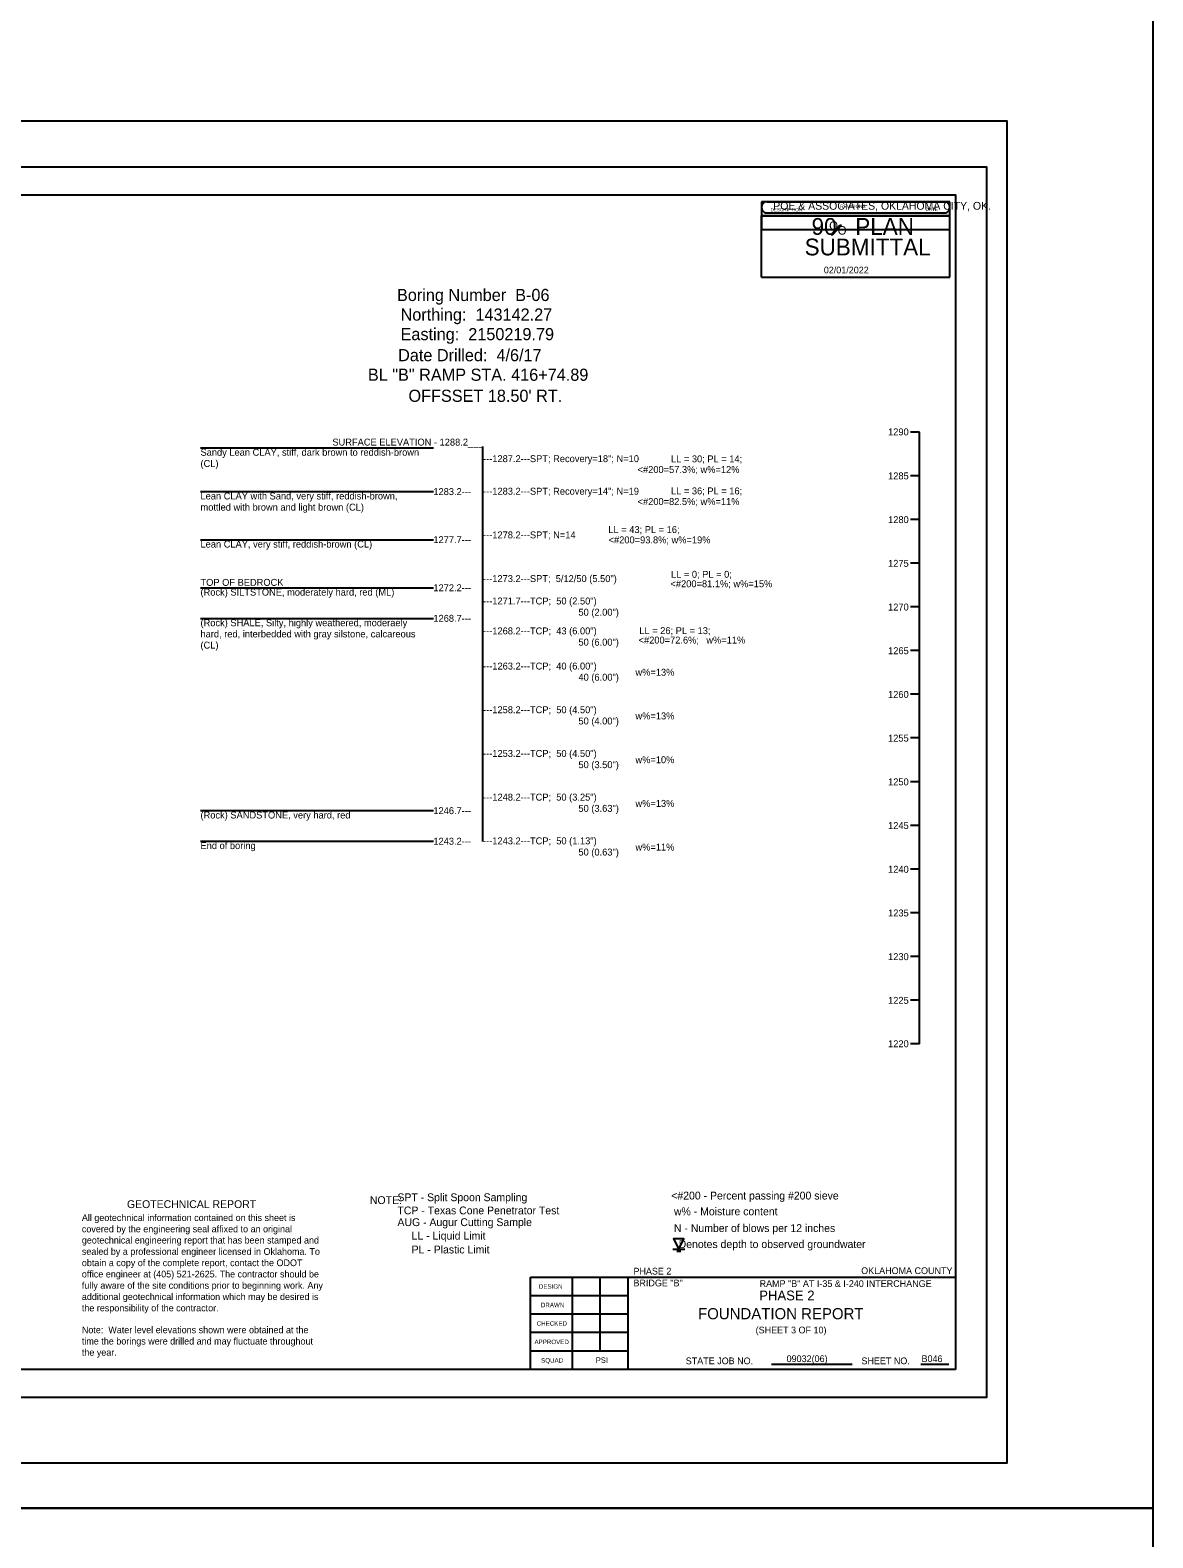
# Model space of a CAD drawing. Extents: x 2150162 to 2150245, y 143729 to 143865.
# Drawn here: x 2150183.34 to 2150203.4, y 143783.81 to 143810.76 of the extents above; entities that cross this region are included whole.
import ezdxf

# ---------------------------------------------------------------- set-up
doc = ezdxf.new("R2010")
doc.units = 0
for name, color, linetype in [('Default', 7, 'Continuous'), ('S', 7, 'Continuous'), ('SHT_Plot_Shape_Full', 7, 'Continuous'), ('SHT_Plot_Shape_Half', 7, 'Continuous'), ('SHT_Sheet_Border', 7, 'Continuous'), ('SHT_Stamp_90_Submit', 7, 'Continuous'), ('SHT_Stamp_Rev_Block', 7, 'Continuous'), ('SHT_Standard_Sheet_Lines', 7, 'Continuous'), ('SHT_Standard_Sheet_Txt', 7, 'Continuous'), ('T', 7, 'Continuous'), ('T-Title', 7, 'Continuous'), ('Text', 7, 'Continuous')]:
    doc.layers.add(name, color=color, linetype=linetype)

# ---------------------------------------------------------------- blocks, each defined once
blk = doc.blocks.new('DGRFC_WTLEV1')
at = {"layer": 'Default'}
for points in [[(-0.0127, 0), (0.0127, 0)], [(0, 0), (0.0106, 0.0212), (-0.0106, 0.0212), (0, 0)], [(-0.0042, -0.0042), (0.0042, -0.0042)]]:
    blk.add_lwpolyline(points, dxfattribs=at)

msp = doc.modelspace()

# ---------------------------------------------------------------- linework, layer by layer
at = {"layer": 'Default'}
msp.add_line((2150199.236, 143792.641), (2150199.236, 143803.578), dxfattribs=at)
for points in [[(2150199.236, 143803.578), (2150199.07, 143803.578)], [(2150186.383, 143803.295), (2150190.55, 143803.295)], [(2150191.421, 143803.322), (2150191.421, 143796.259)], [(2150199.236, 143802.797), (2150199.07, 143802.797)], [(2150186.383, 143802.513), (2150190.55, 143802.513)], [(2150199.236, 143802.015), (2150199.07, 143802.015)], [(2150186.383, 143801.654), (2150190.55, 143801.654)], [(2150199.236, 143801.234), (2150199.07, 143801.234)], [(2150186.383, 143800.795), (2150190.55, 143800.795)], [(2150199.236, 143800.453), (2150199.07, 143800.453)], [(2150186.383, 143800.248), (2150190.55, 143800.248)], [(2150199.236, 143799.672), (2150199.07, 143799.672)], [(2150199.236, 143798.891), (2150199.07, 143798.891)], [(2150199.236, 143798.109), (2150199.07, 143798.109)], [(2150199.236, 143797.328), (2150199.07, 143797.328)], [(2150186.383, 143796.81), (2150190.55, 143796.81)], [(2150199.236, 143796.547), (2150199.07, 143796.547)], [(2150186.383, 143796.263), (2150190.55, 143796.263)], [(2150199.236, 143795.766), (2150199.07, 143795.766)], [(2150199.236, 143794.984), (2150199.07, 143794.984)], [(2150199.236, 143794.203), (2150199.07, 143794.203)], [(2150199.236, 143793.422), (2150199.07, 143793.422)], [(2150199.236, 143792.641), (2150199.07, 143792.641)]]:
    msp.add_lwpolyline(points, dxfattribs=at)
at = {"layer": 'S'}
for points in [[(2150203.404, 143784.341), (2150161.568, 143784.341), (2150161.568, 143865.061), (2150203.404, 143865.061)], [(2150161.568, 143784.341), (2150203.404, 143784.341), (2150203.404, 143729.315), (2150161.568, 143729.315)]]:
    msp.add_lwpolyline(points, close=True, dxfattribs=at)
at = {"layer": 'SHT_Plot_Shape_Full'}
msp.add_lwpolyline([(2150164.792, 143809.144), (2150200.792, 143809.144), (2150200.792, 143785.144), (2150164.792, 143785.144)], close=True, dxfattribs=at)
at = {"layer": 'SHT_Plot_Shape_Half'}
msp.add_lwpolyline([(2150166.429, 143808.319), (2150200.429, 143808.319), (2150200.429, 143786.319), (2150166.429, 143786.319)], close=True, dxfattribs=at)
at = {"layer": 'SHT_Sheet_Border'}
for p, q in [((2150192.279, 143786.819), (2150192.279, 143788.469)), ((2150192.279, 143788.469), (2150199.879, 143788.469)), ((2150194.029, 143786.819), (2150194.029, 143788.47))]:
    msp.add_line(p, q, dxfattribs=at)
msp.add_lwpolyline([(2150199.879, 143786.819), (2150168.379, 143786.819), (2150168.379, 143807.819), (2150199.879, 143807.819)], close=True, dxfattribs=at)
at = {"layer": 'SHT_Stamp_90_Submit'}
for p, q in [((2150196.51, 143807.695), (2150199.676, 143807.695)), ((2150196.41, 143807.445), (2150199.776, 143807.445)), ((2150196.41, 143806.346), (2150196.41, 143807.445)), ((2150196.51, 143807.495), (2150199.676, 143807.495)), ((2150199.776, 143806.346), (2150199.776, 143807.445)), ((2150197.653, 143807.107), (2150197.809, 143807.279)), ((2150197.653, 143807.107), (2150197.684, 143807.107)), ((2150197.671, 143807.107), (2150197.827, 143807.279)), ((2150197.676, 143807.107), (2150197.832, 143807.279)), ((2150197.684, 143807.107), (2150197.839, 143807.279)), ((2150197.809, 143807.279), (2150197.839, 143807.279)), ((2150196.41, 143806.346), (2150199.776, 143806.346))]:
    msp.add_line(p, q, dxfattribs=at)
for centre, start, end in [((2150196.51, 143807.595), 89.9952, 270), ((2150199.676, 143807.595), 270, 90.0048)]:
    msp.add_arc(centre, 0.1, start, end, dxfattribs=at)
at = {"layer": 'SHT_Stamp_Rev_Block'}
for p, q in [((2150196.41, 143807.695), (2150196.41, 143807.195)), ((2150199.776, 143807.695), (2150196.41, 143807.695)), ((2150199.776, 143807.195), (2150199.776, 143807.695)), ((2150199.776, 143807.445), (2150196.41, 143807.445)), ((2150199.776, 143807.195), (2150196.41, 143807.195))]:
    msp.add_line(p, q, dxfattribs=at)
at = {"layer": 'SHT_Standard_Sheet_Lines'}
for p, q in [((2150193.029, 143786.819), (2150193.029, 143788.47)), ((2150193.529, 143787.149), (2150193.529, 143788.47)), ((2150196.59, 143786.915), (2150198.03, 143786.915)), ((2150199.255, 143786.915), (2150199.757, 143786.915))]:
    msp.add_line(p, q, dxfattribs=at)
for points in [[(2150194.029, 143788.139), (2150192.279, 143788.139)], [(2150194.029, 143787.809), (2150192.279, 143787.809)], [(2150194.029, 143787.479), (2150192.279, 143787.479)], [(2150194.029, 143787.149), (2150192.279, 143787.149)]]:
    msp.add_lwpolyline(points, dxfattribs=at)

# ---------------------------------------------------------------- block references
at = {"layer": 'Default', "xscale": 8.503919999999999, "yscale": 8.503919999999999}
msp.add_blockref('DGRFC_WTLEV1', (2150194.93, 143788.973), dxfattribs=at)

# ---------------------------------------------------------------- texts
at = {"layer": 'Default'}
for s, height, p in [('Boring Number  B-06', 0.217, (2150189.895, 143805.92)), ('Northing:  143142.27', 0.217, (2150189.959, 143805.57)), ('Easting:  2150219.79', 0.217, (2150189.959, 143805.22)), ('Date Drilled:  4/6/17', 0.217, (2150189.915, 143804.844)), ('BL "B" RAMP STA. 416+74.89', 0.217, (2150189.375, 143804.494)), ("OFFSSET 18.50' RT.", 0.217, (2150190.1, 143804.118)), ('1290', 0.124, (2150198.672, 143803.519)), ('Sandy Lean CLAY, stiff, dark brown to reddish-brown', 0.124, (2150186.383, 143803.154)), ('SURFACE ELEVATION - 1288.2___', 0.124, (2150188.74, 143803.336)), ('(CL)', 0.124, (2150186.383, 143802.954)), ('---1287.2---SPT; Recovery=18"; N=10', 0.124, (2150191.433, 143803.04)), ('LL = 30; PL = 14;', 0.124, (2150194.792, 143803.036)), ('<#200=57.3%; w%=12%', 0.124, (2150194.195, 143802.846)), ('1285', 0.124, (2150198.672, 143802.732)), ('Lean CLAY with Sand, very stiff, reddish-brown,', 0.124, (2150186.383, 143802.373)), ('1283.2---', 0.124, (2150190.545, 143802.451)), ('---1283.2---SPT; Recovery=14"; N=19', 0.124, (2150191.433, 143802.458)), ('LL = 36; PL = 16;', 0.124, (2150194.792, 143802.463)), ('mottled with brown and light brown (CL)', 0.124, (2150186.383, 143802.173)), ('<#200=82.5%; w%=11%', 0.124, (2150194.195, 143802.273)), ('1280', 0.124, (2150198.672, 143801.95)), ('Lean CLAY, very stiff, reddish-brown (CL)', 0.124, (2150186.383, 143801.513)), ('1277.7---', 0.124, (2150190.545, 143801.592)), ('---1278.2---SPT; N=14', 0.124, (2150191.433, 143801.677)), ('<#200=93.8%; w%=19%', 0.124, (2150193.677, 143801.588)), ('LL = 43; PL = 16;', 0.124, (2150193.673, 143801.773)), ('LL = 0; PL = 0;', 0.124, (2150194.792, 143800.973)), ('1275', 0.124, (2150198.672, 143801.169)), ('TOP OF BEDROCK', 0.124, (2150186.383, 143800.829)), ('1272.2---', 0.124, (2150190.545, 143800.733)), ('---1273.2---SPT;  5/12/50 (5.50")', 0.124, (2150191.433, 143800.896)), ('<#200=81.1%%%; w%%%=15%%%', 0.124, (2150194.783, 143800.804)), ('(Rock) SILTSTONE, moderately hard, red (ML)', 0.124, (2150186.383, 143800.654)), ('---1271.7---TCP;  50 (2.50")', 0.124, (2150191.433, 143800.496)), ('1268.7---', 0.124, (2150190.545, 143800.186)), ('50 (2.00")', 0.124, (2150193.138, 143800.295)), ('1270', 0.124, (2150198.672, 143800.388)), ('(Rock) SHALE, Silty, highly weathered, moderaely', 0.124, (2150186.383, 143800.107)), ('hard, red, interbedded with gray silstone, calcareous', 0.124, (2150186.383, 143799.907)), ('---1268.2---TCP;  43 (6.00")', 0.124, (2150191.433, 143799.961)), ('LL = 26; PL = 13;', 0.124, (2150194.226, 143799.966)), ('(CL)', 0.124, (2150186.383, 143799.707)), ('50 (6.00")', 0.124, (2150193.138, 143799.76)), ('<#200=72.6%;', 0.124, (2150194.213, 143799.797)), ('w%=11%', 0.124, (2150195.424, 143799.798)), ('1265', 0.124, (2150198.672, 143799.607)), ('---1263.2---TCP;  40 (6.00")', 0.124, (2150191.433, 143799.333)), ('40 (6.00")', 0.124, (2150193.138, 143799.133)), ('w%=13%', 0.124, (2150194.157, 143799.222)), ('1260', 0.124, (2150198.672, 143798.825)), ('---1258.2---TCP;  50 (4.50")', 0.124, (2150191.433, 143798.552)), ('50 (4.00")', 0.124, (2150193.138, 143798.351)), ('w%=13%', 0.124, (2150194.157, 143798.441)), ('1255', 0.124, (2150198.672, 143798.044)), ('---1253.2---TCP;  50 (4.50")', 0.124, (2150191.433, 143797.771)), ('50 (3.50")', 0.124, (2150193.138, 143797.57)), ('w%=10%', 0.124, (2150194.157, 143797.659)), ('1250', 0.124, (2150198.672, 143797.263)), ('---1248.2---TCP;  50 (3.25")', 0.124, (2150191.433, 143796.99)), ('(Rock) SANDSTONE, very hard, red', 0.124, (2150186.383, 143796.67)), ('1246.7---', 0.124, (2150190.545, 143796.748)), ('50 (3.63")', 0.124, (2150193.138, 143796.789)), ('w%=13%', 0.124, (2150194.157, 143796.878)), ('1245', 0.124, (2150198.672, 143796.482)), ('End of boring', 0.124, (2150186.383, 143796.123)), ('1243.2---', 0.124, (2150190.545, 143796.201)), ('---1243.2---TCP;  50 (1.13")', 0.124, (2150191.433, 143796.208)), ('50 (0.63")', 0.124, (2150193.138, 143796.008)), ('w%=11%', 0.124, (2150194.157, 143796.097)), ('1240', 0.124, (2150198.672, 143795.7)), ('1235', 0.124, (2150198.672, 143794.919)), ('1230', 0.124, (2150198.672, 143794.138)), ('1225', 0.124, (2150198.672, 143793.357)), ('1220', 0.124, (2150198.672, 143792.581))]:
    msp.add_text(s, height=height, dxfattribs=at).set_placement(p)
at = {"layer": 'Defpoints'}
msp.add_text('PHASE 2', height=0.175, dxfattribs=at).set_placement((2150196.369, 143788.056))
at = {"layer": 'SHT_Stamp_90_Submit'}
for s, height, p in [('POE & ASSOCIATES, OKLAHOMA CITY, OK.', 0.14, (2150196.62, 143807.552)), ('90   PLAN', 0.3, (2150197.305, 143807.103)), ('O', 0.153, (2150197.619, 143807.192)), ('SUBMITTAL', 0.3, (2150197.181, 143806.736)), ('O', 0.153, (2150197.771, 143807.107)), ('02/01/2022', 0.12, (2150197.523, 143806.414))]:
    msp.add_text(s, height=height, dxfattribs=at).set_placement(p)
at = {"layer": 'SHT_Stamp_Rev_Block'}
for s, height, p in [('DESCRIPTION', 0.05999, (2150196.57, 143807.523)), ('REVISIONS', 0.06, (2150197.818, 143807.582)), ('DATE', 0.06, (2150199.34, 143807.527))]:
    msp.add_text(s, height=height, dxfattribs=at).set_placement(p)
at = {"layer": 'SHT_Standard_Sheet_Txt'}
for s, height, p in [('DESIGN', 0.08, (2150192.431, 143788.264)), ('DRAWN', 0.08, (2150192.467, 143787.934)), ('CHECKED', 0.08, (2150192.392, 143787.604)), ('APPROVED', 0.08, (2150192.353, 143787.274)), ('SQUAD', 0.08, (2150192.471, 143786.943)), ('STATE JOB NO.', 0.12, (2150195.056, 143786.915)), ('SHEET NO. ', 0.12, (2150198.196, 143786.915))]:
    msp.add_text(s, height=height, dxfattribs=at).set_placement(p)
at = {"layer": 'T'}
for s, height, p in [('PHASE 2', 0.12, (2150194.121, 143788.518)), ('BRIDGE "B"', 0.12, (2150194.121, 143788.307)), ('OKLAHOMA COUNTY', 0.12, (2150198.191, 143788.526)), ('RAMP "B" AT I-35 & I-240 INTERCHANGE', 0.12, (2150196.376, 143788.296)), ('(SHEET 3 OF 10)', 0.12, (2150196.305, 143787.466)), ('PSI', 0.1, (2150193.449, 143786.937)), ('09032(06)', 0.12, (2150196.859, 143786.953)), ('B046', 0.12, (2150199.27, 143786.953))]:
    msp.add_text(s, height=height, dxfattribs=at).set_placement(p)
at = {"layer": 'T-Title'}
msp.add_text('FOUNDATION REPORT', height=0.2, dxfattribs=at).set_placement((2150195.276, 143787.718))
at = {"layer": 'Text'}
for s, height, p in [('GEOTECHNICAL REPORT', 0.14, (2150185.069, 143789.706)), ('NOTE:', 0.14, (2150189.411, 143789.778)), ('    SPT - Split Spoon Sampling', 0.14, (2150189.695, 143789.829)), (' <#200 - Percent passing #200 sieve', 0.14, (2150194.745, 143789.859)), ('All geotechnical information contained on this sheet is ', 0.12, (2150184.263, 143789.474)), ('    AUG - Augur Cutting Sample', 0.14, (2150189.695, 143789.384)), ('    TCP - Texas Cone Penetrator Test', 0.14, (2150189.695, 143789.594)), ('w% - Moisture content', 0.14, (2150194.845, 143789.577)), ('covered by the engineering seal affixed to an original ', 0.12, (2150184.263, 143789.272)), (' LL - Liquid Limit', 0.14, (2150190.104, 143789.142)), ('N - Number of blows per 12 inches', 0.14, (2150194.845, 143789.278)), ('sealed by a professional engineer licensed in Oklahoma. To ', 0.12, (2150184.263, 143788.87)), ('geotechnical engineering report that has been stamped and ', 0.12, (2150184.263, 143789.072)), (' PL - Plastic Limit', 0.14, (2150190.104, 143788.895)), ('    Denotes depth to observed groundwater', 0.14, (2150194.721, 143788.991)), ('obtain a copy of the complete report, contact the ODOT ', 0.12, (2150184.263, 143788.668)), ('office engineer at (405) 521-2625. The contractor should be ', 0.12, (2150184.263, 143788.466)), ('fully aware of the site conditions prior to beginning work. Any ', 0.12, (2150184.263, 143788.264)), ('additional geotechnical information which may be desired is ', 0.12, (2150184.263, 143788.062)), ('the responsibility of the contractor.', 0.12, (2150184.263, 143787.86)), ('time the borings were drilled and may fluctuate throughout ', 0.12, (2150184.263, 143787.267)), ('Note:  Water level elevations shown were obtained at the ', 0.12, (2150184.263, 143787.469)), ('the year.', 0.12, (2150184.263, 143787.067))]:
    msp.add_text(s, height=height, dxfattribs=at).set_placement(p)

doc.saveas('drawing.dxf')
